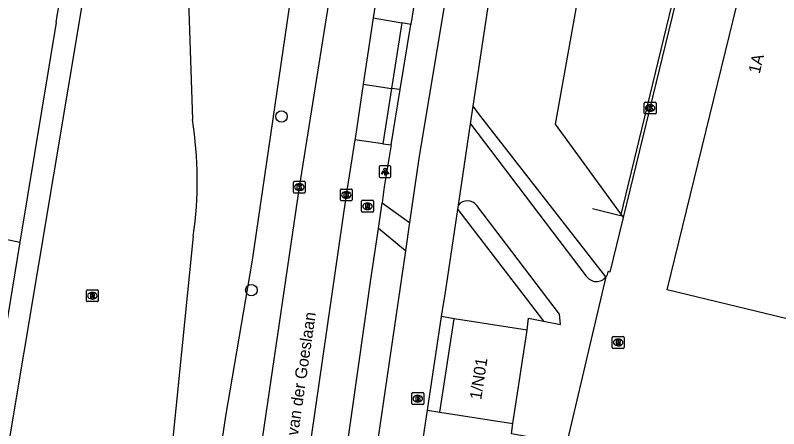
# Model space of a CAD drawing. Extents: x 163046 to 165074, y 382019 to 382874.
# Drawn here: x 163119.9 to 163184.8, y 382777.8 to 382812.9 of the extents above; entities that cross this region are included whole.
import ezdxf

# ---------------------------------------------------------------- set-up
doc = ezdxf.new("R2010")
doc.units = 0
for name, color, linetype in [('IMGEO_Berm_groen', 7, 'Continuous'), ('IMGEO_Berm_halfverhard', 7, 'Continuous'), ('IMGEO_Boom', 7, 'Continuous'), ('IMGEO_Brandkraan', 7, 'Continuous'), ('IMGEO_Fietspad_gesloten', 7, 'Continuous'), ('IMGEO_Fietspad_open', 7, 'Continuous'), ('IMGEO_Groenvoorziening', 7, 'Continuous'), ('IMGEO_Hek', 7, 'Continuous'), ('IMGEO_Kolk', 7, 'Continuous'), ('IMGEO_Lichtpunt', 7, 'Continuous'), ('IMGEO_Openbare_ruimte_label', 7, 'Continuous'), ('IMGEO_Pand', 7, 'Continuous'), ('IMGEO_Pand_nummerreeks', 7, 'Continuous'), ('IMGEO_Parkeervlak_open', 7, 'Continuous'), ('IMGEO_Rijbaan_lokaal_gesloten', 7, 'Continuous'), ('IMGEO_Rijbaan_lokaal_open', 7, 'Continuous'), ('IMGEO_Rioolput', 7, 'Continuous'), ('IMGEO_Voetpad_halfverhard', 7, 'Continuous'), ('IMGEO_Voetpad_open', 7, 'Continuous')]:
    doc.layers.add(name, color=color, linetype=linetype)

msp = doc.modelspace()

# ---------------------------------------------------------------- linework, layer by layer
at = {"layer": 'IMGEO_Berm_groen'}
for points in [[(163117.196, 382766.95), (163119.444, 382776.857), (163125.716, 382814.214), (163129.752, 382841.072)], [(163144.103, 382835.721), (163143.26, 382822.615), (163143.707, 382817.037), (163140.066, 382792.087), (163137.776, 382778.86), (163133.466, 382750), (163130.056, 382727.169)], [(163134.545, 382817.473), (163134.992, 382804.003)], [(163123.418, 382812.236), (163120.341, 382793.612)], [(163115.63, 382794.599), (163120.341, 382793.612)], [(163120.341, 382793.612), (163118.136, 382780.262)], [(163135.056, 382794.132), (163131.605, 382759.828), (163131.17, 382753.793), (163131.079, 382750), (163130.908, 382742.92), (163130.056, 382727.169)]]:
    msp.add_lwpolyline(points, dxfattribs=at)
for centre, radius, start, end in [((163009.489, 382831.398), 115.53, 350.45256, 356.35077), ((163101.746, 382798.852), 33.643, 351.93545, 8.80751)]:
    msp.add_arc(centre, radius, start, end, dxfattribs=at)
at = {"layer": 'IMGEO_Berm_halfverhard'}
for points in [[(163170.081, 382790.666), (163159.263, 382804.526), (163158.823, 382805.145)], [(163157.504, 382796.382), (163163.68, 382788.362), (163164.793, 382786.917)]]:
    msp.add_lwpolyline(points, dxfattribs=at)
at = {"layer": 'IMGEO_Boom'}
for centre in [(163142.541, 382804.272), (163139.988, 382789.546)]:
    msp.add_circle(centre, 0.489, dxfattribs=at)
at = {"layer": 'IMGEO_Brandkraan'}
for p, q in [((163153.61, 382779.927), (163153.61, 382780.779)), ((163153.685, 382780.853), (163154.537, 382780.853)), ((163154.611, 382780.779), (163154.611, 382779.927)), ((163154.121, 382780.073), (163154.096, 382780.073)), ((163154.098, 382780.633), (163154.123, 382780.633)), ((163154.537, 382779.853), (163153.685, 382779.853))]:
    msp.add_line(p, q, dxfattribs=at)
for points in [[(163153.61, 382779.927), (163153.61, 382780.779)], [(163153.685, 382780.853), (163154.537, 382780.853)], [(163154.611, 382780.779), (163154.611, 382779.927)], [(163153.958, 382780.553), (163153.958, 382780.153), (163154.171, 382780.153)], [(163154.189, 382780.553), (163153.958, 382780.553)], [(163154.137, 382780.472), (163154.083, 382780.472), (163154.083, 382780.396)], [(163154.083, 382780.396), (163154.136, 382780.396)], [(163154.145, 382780.32), (163154.083, 382780.32), (163154.083, 382780.239)], [(163154.083, 382780.239), (163154.145, 382780.239)], [(163154.537, 382779.853), (163153.685, 382779.853)]]:
    msp.add_lwpolyline(points, dxfattribs=at)
for centre, radius, start, end in [((163153.687, 382780.777), 0.0765, 91.55205, 178.44795), ((163153.687, 382780.777), 0.0765, 91.55205, 178.44795), ((163154.535, 382780.777), 0.0765, 1.55205, 88.44795), ((163154.535, 382780.777), 0.0765, 1.55205, 88.44795), ((163154.138, 382780.434), 0.0379, 267.82845, 90.93552), ((163154.146, 382780.279), 0.0404, 269.87594, 90.50774), ((163154.177, 382780.404), 0.251, 268.66757, 293.53466), ((163154.193, 382780.408), 0.145, 59.4692, 91.53667), ((163154.218, 382780.455), 0.0922, 285.51372, 58.15012), ((163154.223, 382780.263), 0.105, 301.31148, 78.98903), ((163153.687, 382779.929), 0.0765, 181.55205, 268.44795), ((163153.687, 382779.929), 0.0765, 181.55205, 268.44795), ((163154.535, 382779.929), 0.0765, 271.55205, 358.44795), ((163154.535, 382779.929), 0.0765, 271.55205, 358.44795)]:
    msp.add_arc(centre, radius, start, end, dxfattribs=at)
for centre, major_axis, ratio, start_param, end_param in [((163154.097, 382780.353), (-0.387, 0.002), 0.722429, 4.712389, 7.853982), ((163154.122, 382780.353), (-0.39, 0.002), 0.717154, 1.570796, 4.712389)]:
    msp.add_ellipse(centre, major_axis=major_axis, ratio=ratio, start_param=start_param, end_param=end_param, dxfattribs=at)
at = {"layer": 'IMGEO_Fietspad_gesloten'}
for points in [[(163161.113, 382845.228), (163160.864, 382844.839), (163160.254, 382840.645), (163156.415, 382813.95), (163154.228, 382800.916), (163153.406, 382795.273)], [(163157.332, 382836.53), (163153.568, 382812.405), (163153.528, 382812.16), (163153.515, 382812.081)], [(163151.849, 382801.853), (163152.616, 382806.559)], [(163151.849, 382801.853), (163151.271, 382798.302), (163151.077, 382796.956)], [(163151.077, 382796.956), (163153.406, 382795.273)], [(163147.509, 382772.212), (163147.935, 382775.112), (163150.138, 382790.439), (163150.763, 382794.772)], [(163153.058, 382792.885), (163150.763, 382794.772)], [(163153.058, 382792.885), (163150.245, 382773.595), (163147.259, 382753.463), (163143.616, 382727.869), (163141.748, 382715.527), (163141.421, 382713.325)]]:
    msp.add_lwpolyline(points, dxfattribs=at)
at = {"layer": 'IMGEO_Fietspad_open'}
for points in [[(163150.763, 382794.772), (163151.077, 382796.956)], [(163153.406, 382795.273), (163153.058, 382792.885)]]:
    msp.add_lwpolyline(points, dxfattribs=at)
at = {"layer": 'IMGEO_Groenvoorziening'}
for points in [[(163173.417, 382846.227), (163165.783, 382803.624), (163171.545, 382795.713)], [(163182.274, 382837.906), (163182.21, 382837.622), (163181.791, 382837.701), (163171.545, 382795.713)], [(163171.545, 382795.713), (163170.414, 382791.078), (163170.285, 382791.115)]]:
    msp.add_lwpolyline(points, dxfattribs=at)
msp.add_arc((163169.266, 382791.307), 1.037, 321.80581, 349.32551, dxfattribs=at)
at = {"layer": 'IMGEO_Hek'}
msp.add_lwpolyline([(163182.274, 382837.906), (163181.977, 382837.967), (163181.572, 382838.061), (163171.308, 382795.842), (163168.94, 382796.432)], dxfattribs=at)
at = {"layer": 'IMGEO_Kolk'}
for p, q in [((163173.336, 382804.562), (163173.336, 382805.414)), ((163173.411, 382805.488), (163174.263, 382805.488)), ((163173.824, 382805.268), (163173.849, 382805.268)), ((163174.337, 382805.414), (163174.337, 382804.562)), ((163173.847, 382804.708), (163173.822, 382804.708)), ((163174.263, 382804.488), (163173.411, 382804.488)), ((163143.632, 382798.78), (163144.484, 382798.78)), ((163143.557, 382797.854), (163143.557, 382798.706)), ((163144.045, 382798.56), (163144.07, 382798.56)), ((163144.558, 382798.706), (163144.558, 382797.854)), ((163144.484, 382797.78), (163143.632, 382797.78)), ((163144.068, 382798), (163144.043, 382798)), ((163147.545, 382797.19), (163147.545, 382798.042)), ((163147.62, 382798.116), (163148.472, 382798.116)), ((163148.033, 382797.896), (163148.058, 382797.896)), ((163148.546, 382798.042), (163148.546, 382797.19)), ((163148.472, 382797.116), (163147.62, 382797.116)), ((163148.056, 382797.336), (163148.031, 382797.336))]:
    msp.add_line(p, q, dxfattribs=at)
for points in [[(163173.336, 382804.562), (163173.336, 382805.414)], [(163173.411, 382805.488), (163174.263, 382805.488)], [(163174.337, 382805.414), (163174.337, 382804.562)], [(163173.657, 382805.188), (163173.78, 382805.188), (163173.78, 382805.037), (163173.91, 382805.188), (163174.074, 382805.188), (163173.928, 382805.037), (163174.081, 382804.788), (163173.929, 382804.788), (163173.844, 382804.952), (163173.78, 382804.885), (163173.78, 382804.788), (163173.657, 382804.788), (163173.657, 382805.188)], [(163174.263, 382804.488), (163173.411, 382804.488)], [(163143.632, 382798.78), (163144.484, 382798.78)], [(163143.557, 382797.854), (163143.557, 382798.706)], [(163143.878, 382798.48), (163144.001, 382798.48), (163144.001, 382798.329), (163144.131, 382798.48), (163144.295, 382798.48), (163144.149, 382798.329), (163144.302, 382798.08), (163144.15, 382798.08), (163144.065, 382798.244), (163144.001, 382798.177), (163144.001, 382798.08), (163143.878, 382798.08), (163143.878, 382798.48)], [(163144.558, 382798.706), (163144.558, 382797.854)], [(163144.484, 382797.78), (163143.632, 382797.78)], [(163147.545, 382797.19), (163147.545, 382798.042)], [(163147.62, 382798.116), (163148.472, 382798.116)], [(163147.866, 382797.816), (163147.989, 382797.816), (163147.989, 382797.665), (163148.119, 382797.816), (163148.283, 382797.816), (163148.137, 382797.665), (163148.29, 382797.416), (163148.138, 382797.416), (163148.053, 382797.58), (163147.989, 382797.513), (163147.989, 382797.416), (163147.866, 382797.416), (163147.866, 382797.816)], [(163148.546, 382798.042), (163148.546, 382797.19)], [(163148.472, 382797.116), (163147.62, 382797.116)]]:
    msp.add_lwpolyline(points, dxfattribs=at)
for centre, start, end in [((163173.413, 382805.412), 91.55205, 178.44795), ((163173.413, 382805.412), 91.55205, 178.44795), ((163174.261, 382805.412), 1.55205, 88.44795), ((163174.261, 382805.412), 1.55205, 88.44795), ((163173.413, 382804.564), 181.55205, 268.44795), ((163173.413, 382804.564), 181.55205, 268.44795), ((163174.261, 382804.564), 271.55205, 358.44795), ((163174.261, 382804.564), 271.55205, 358.44795), ((163143.634, 382798.704), 91.55205, 178.44795), ((163143.634, 382798.704), 91.55205, 178.44795), ((163144.482, 382798.704), 1.55205, 88.44795), ((163144.482, 382798.704), 1.55205, 88.44795), ((163143.634, 382797.856), 181.55205, 268.44795), ((163143.634, 382797.856), 181.55205, 268.44795), ((163144.482, 382797.856), 271.55205, 358.44795), ((163144.482, 382797.856), 271.55205, 358.44795), ((163147.622, 382798.04), 91.55205, 178.44795), ((163147.622, 382798.04), 91.55205, 178.44795), ((163148.47, 382798.04), 1.55205, 88.44795), ((163148.47, 382798.04), 1.55205, 88.44795), ((163147.622, 382797.192), 181.55205, 268.44795), ((163147.622, 382797.192), 181.55205, 268.44795), ((163148.47, 382797.192), 271.55205, 358.44795), ((163148.47, 382797.192), 271.55205, 358.44795)]:
    msp.add_arc(centre, 0.0765, start, end, dxfattribs=at)
for centre, major_axis, ratio, start_param, end_param in [((163173.823, 382804.988), (-0.387, 0.002), 0.722429, 4.712389, 7.853982), ((163173.848, 382804.988), (-0.39, 0.002), 0.717154, 1.570796, 4.712389), ((163144.044, 382798.28), (-0.387, 0.002), 0.722429, 4.712389, 7.853982), ((163144.069, 382798.28), (-0.39, 0.002), 0.717154, 1.570796, 4.712389), ((163148.032, 382797.616), (-0.387, 0.002), 0.722429, 4.712389, 7.853982), ((163148.057, 382797.616), (-0.39, 0.002), 0.717154, 1.570796, 4.712389)]:
    msp.add_ellipse(centre, major_axis=major_axis, ratio=ratio, start_param=start_param, end_param=end_param, dxfattribs=at)
at = {"layer": 'IMGEO_Lichtpunt'}
for p, q in [((163151.74, 382800.097), (163150.932, 382800.097)), ((163151.74, 382800.097), (163150.932, 382800.097)), ((163150.838, 382800.002), (163150.838, 382799.195)), ((163150.838, 382800.002), (163150.838, 382799.195)), ((163151.834, 382799.195), (163151.834, 382800.002)), ((163151.834, 382799.195), (163151.834, 382800.002)), ((163150.932, 382799.101), (163151.74, 382799.101)), ((163150.932, 382799.101), (163151.74, 382799.101))]:
    msp.add_line(p, q, dxfattribs=at)
for points in [[(163151.212, 382799.666), (163151.251, 382799.638), (163151.063, 382799.376), (163151.025, 382799.403), (163151.212, 382799.666)], [(163151.314, 382799.618), (163151.361, 382799.618), (163151.361, 382799.296), (163151.314, 382799.296), (163151.314, 382799.618)], [(163151.424, 382799.638), (163151.462, 382799.665), (163151.649, 382799.403), (163151.61, 382799.375), (163151.424, 382799.638)]]:
    msp.add_lwpolyline(points, dxfattribs=at)
msp.add_circle((163151.337, 382799.8), 0.0994, dxfattribs=at)
for centre, start, end in [((163150.932, 382800.002), 90, 180), ((163150.932, 382800.002), 90, 180), ((163151.74, 382800.002), 0, 90), ((163151.74, 382800.002), 0, 90), ((163150.932, 382799.195), 180, 270), ((163150.932, 382799.195), 180, 270), ((163151.74, 382799.195), 270, 0), ((163151.74, 382799.195), 270, 360)]:
    msp.add_arc(centre, 0.0946, start, end, dxfattribs=at)
at = {"layer": 'IMGEO_Pand'}
for points in [[(163187.293, 382745.549), (163188.39, 382750), (163192.114, 382765.114), (163195.861, 382780.592), (163193.706, 382781.12), (163194.64, 382784.88), (163189.274, 382786.194), (163188.807, 382784.289), (163185.83, 382784.999), (163186.289, 382786.912), (163175.289, 382789.564), (163181.211, 382813.835), (163184.927, 382829.066), (163223.479, 382819.666), (163229.289, 382818.246), (163225.61, 382803.159), (163234.14, 382801.079), (163234.934, 382804.334), (163235.333, 382804.237), (163228.809, 382777.497)], [(163155.996, 382779.19), (163157.203, 382787.107)], [(163163.387, 382786.165), (163157.203, 382787.107)], [(163162.18, 382778.247), (163163.387, 382786.165)], [(163155.996, 382779.19), (163162.18, 382778.247)]]:
    msp.add_lwpolyline(points, dxfattribs=at)
at = {"layer": 'IMGEO_Parkeervlak_open'}
msp.add_lwpolyline([(163151.156, 382801.951), (163148.773, 382802.288)], dxfattribs=at)
at = {"layer": 'IMGEO_Rijbaan_lokaal_gesloten'}
for points in [[(163133.078, 382728.993), (163133.75, 382730.587), (163134.348, 382732.415), (163134.652, 382734.165), (163134.996, 382736.383), (163136.998, 382750), (163137.687, 382754.683), (163140.785, 382775.983), (163144.059, 382798.28), (163147.602, 382820.471), (163149.65, 382831.634)], [(163153.583, 382830.888), (163150.907, 382816.447), (163150.331, 382812.628)], [(163150.331, 382812.628), (163149.485, 382807.011)], [(163149.485, 382807.011), (163148.791, 382802.404), (163148.773, 382802.288)], [(163148.773, 382802.288), (163148.045, 382797.616), (163144.417, 382772.599)]]:
    msp.add_lwpolyline(points, dxfattribs=at)
at = {"layer": 'IMGEO_Rijbaan_lokaal_open'}
for points in [[(163150.331, 382812.628), (163152.761, 382812.211)], [(163152.761, 382812.211), (163151.891, 382806.653)], [(163152.616, 382806.559), (163153.515, 382812.081)], [(163153.515, 382812.081), (163152.761, 382812.211)], [(163149.485, 382807.011), (163151.891, 382806.653)], [(163152.616, 382806.559), (163151.891, 382806.653)], [(163157.56, 382796.752), (163158.596, 382803.635)], [(163158.596, 382803.635), (163168.418, 382790.74)], [(163164.793, 382786.917), (163166.223, 382786.643), (163166.127, 382787.521), (163159.112, 382796.727)], [(163170.081, 382790.666), (163166.826, 382776.841), (163169.382, 382776.239), (163169.071, 382774.966)], [(163163.387, 382786.165), (163163.519, 382787.161), (163164.793, 382786.917)], [(163164.114, 382776.987), (163162.054, 382777.371), (163162.18, 382778.247)]]:
    msp.add_lwpolyline(points, dxfattribs=at)
for centre, radius, start, end in [((163158.326, 382796.131), 0.986, 37.19432, 140.95997), ((163169.276, 382791.301), 1.025, 213.19167, 321.71261)]:
    msp.add_arc(centre, radius, start, end, dxfattribs=at)
at = {"layer": 'IMGEO_Rioolput'}
for p, q in [((163149.343, 382796.237), (163149.343, 382797.089)), ((163149.418, 382797.163), (163150.27, 382797.163)), ((163149.831, 382796.943), (163149.856, 382796.943)), ((163150.344, 382797.089), (163150.344, 382796.237)), ((163149.854, 382796.383), (163149.829, 382796.383)), ((163150.27, 382796.163), (163149.418, 382796.163)), ((163125.988, 382788.643), (163125.988, 382789.495)), ((163126.063, 382789.569), (163126.915, 382789.569)), ((163126.476, 382789.349), (163126.501, 382789.349)), ((163126.989, 382789.495), (163126.989, 382788.643)), ((163126.915, 382788.569), (163126.063, 382788.569)), ((163126.499, 382788.789), (163126.474, 382788.789)), ((163170.618, 382784.682), (163170.618, 382785.534)), ((163170.693, 382785.608), (163171.545, 382785.608)), ((163171.106, 382785.388), (163171.131, 382785.388)), ((163171.619, 382785.534), (163171.619, 382784.682)), ((163171.545, 382784.608), (163170.693, 382784.608)), ((163171.129, 382784.828), (163171.104, 382784.828))]:
    msp.add_line(p, q, dxfattribs=at)
for points in [[(163149.343, 382796.237), (163149.343, 382797.089)], [(163149.418, 382797.163), (163150.27, 382797.163)], [(163149.932, 382796.861), (163149.68, 382796.863), (163149.68, 382796.463)], [(163150.344, 382797.089), (163150.344, 382796.237)], [(163149.68, 382796.463), (163149.804, 382796.463), (163149.804, 382796.625), (163149.815, 382796.625)], [(163149.858, 382796.782), (163149.804, 382796.782), (163149.804, 382796.701)], [(163149.804, 382796.701), (163149.856, 382796.701)], [(163149.862, 382796.596), (163149.933, 382796.463), (163150.073, 382796.463), (163150.008, 382796.589)], [(163150.27, 382796.163), (163149.418, 382796.163)], [(163125.988, 382788.643), (163125.988, 382789.495)], [(163126.063, 382789.569), (163126.915, 382789.569)], [(163126.577, 382789.267), (163126.325, 382789.269), (163126.325, 382788.869)], [(163126.503, 382789.188), (163126.449, 382789.188), (163126.449, 382789.107)], [(163126.449, 382789.107), (163126.501, 382789.107)], [(163126.989, 382789.495), (163126.989, 382788.643)], [(163126.915, 382788.569), (163126.063, 382788.569)], [(163126.325, 382788.869), (163126.449, 382788.869), (163126.449, 382789.031), (163126.46, 382789.031)], [(163126.507, 382789.002), (163126.578, 382788.869), (163126.718, 382788.869), (163126.653, 382788.995)], [(163170.618, 382784.682), (163170.618, 382785.534)], [(163170.693, 382785.608), (163171.545, 382785.608)], [(163171.207, 382785.306), (163170.955, 382785.308), (163170.955, 382784.908)], [(163171.133, 382785.227), (163171.079, 382785.227), (163171.079, 382785.146)], [(163171.619, 382785.534), (163171.619, 382784.682)], [(163171.545, 382784.608), (163170.693, 382784.608)], [(163170.955, 382784.908), (163171.079, 382784.908), (163171.079, 382785.07), (163171.09, 382785.07)], [(163171.079, 382785.146), (163171.131, 382785.146)], [(163171.137, 382785.041), (163171.208, 382784.908), (163171.348, 382784.908), (163171.283, 382785.034)]]:
    msp.add_lwpolyline(points, dxfattribs=at)
for centre, radius, start, end in [((163149.42, 382797.087), 0.0765, 91.55205, 178.44795), ((163149.42, 382797.087), 0.0765, 91.55205, 178.44795), ((163149.931, 382796.751), 0.109, 350.36119, 89.41601), ((163150.268, 382797.087), 0.0765, 1.55205, 88.44795), ((163150.268, 382797.087), 0.0765, 1.55205, 88.44795), ((163149.42, 382796.239), 0.0765, 181.55205, 268.44795), ((163149.42, 382796.239), 0.0765, 181.55205, 268.44795), ((163149.814, 382796.572), 0.0533, 26.02933, 88.69889), ((163149.84, 382796.89), 0.19, 274.7715, 282.96867), ((163149.864, 382796.686), 0.0964, 77.00612, 93.18647), ((163149.878, 382796.743), 0.0378, 276.66336, 79.67722), ((163149.929, 382796.751), 0.112, 277.58423, 350.98172), ((163149.913, 382796.536), 0.108, 29.51342, 73.79051), ((163150.268, 382796.239), 0.0765, 271.55205, 358.44795), ((163150.268, 382796.239), 0.0765, 271.55205, 358.44795), ((163126.065, 382789.493), 0.0765, 91.55205, 178.44795), ((163126.065, 382789.493), 0.0765, 91.55205, 178.44795), ((163126.485, 382789.296), 0.19, 274.7715, 282.96867), ((163126.509, 382789.092), 0.0964, 77.00612, 93.18647), ((163126.523, 382789.149), 0.0378, 276.66336, 79.67722), ((163126.576, 382789.157), 0.109, 350.36119, 89.41601), ((163126.574, 382789.157), 0.112, 277.58423, 350.98172), ((163126.913, 382789.493), 0.0765, 1.55205, 88.44795), ((163126.913, 382789.493), 0.0765, 1.55205, 88.44795), ((163126.065, 382788.645), 0.0765, 181.55205, 268.44795), ((163126.065, 382788.645), 0.0765, 181.55205, 268.44795), ((163126.459, 382788.978), 0.0533, 26.02933, 88.69889), ((163126.558, 382788.942), 0.108, 29.51342, 73.79051), ((163126.913, 382788.645), 0.0765, 271.55205, 358.44795), ((163126.913, 382788.645), 0.0765, 271.55205, 358.44795), ((163170.695, 382785.532), 0.0765, 91.55205, 178.44795), ((163170.695, 382785.532), 0.0765, 91.55205, 178.44795), ((163171.139, 382785.131), 0.0964, 77.00612, 93.18647), ((163171.153, 382785.188), 0.0378, 276.66336, 79.67722), ((163171.206, 382785.196), 0.109, 350.36119, 89.41601), ((163171.204, 382785.196), 0.112, 277.58423, 350.98172), ((163171.543, 382785.532), 0.0765, 1.55205, 88.44795), ((163171.543, 382785.532), 0.0765, 1.55205, 88.44795), ((163170.695, 382784.684), 0.0765, 181.55205, 268.44795), ((163170.695, 382784.684), 0.0765, 181.55205, 268.44795), ((163171.089, 382785.017), 0.0533, 26.02933, 88.69889), ((163171.115, 382785.335), 0.19, 274.7715, 282.96867), ((163171.188, 382784.981), 0.108, 29.51342, 73.79051), ((163171.543, 382784.684), 0.0765, 271.55205, 358.44795), ((163171.543, 382784.684), 0.0765, 271.55205, 358.44795)]:
    msp.add_arc(centre, radius, start, end, dxfattribs=at)
for centre, major_axis, ratio, start_param, end_param in [((163149.83, 382796.663), (-0.387, 0.002), 0.722429, 4.712389, 7.853982), ((163149.855, 382796.663), (-0.39, 0.002), 0.717154, 1.570796, 4.712389), ((163126.475, 382789.069), (-0.387, 0.002), 0.722429, 4.712389, 7.853982), ((163126.5, 382789.069), (-0.39, 0.002), 0.717154, 1.570796, 4.712389), ((163171.105, 382785.108), (-0.387, 0.002), 0.722429, 4.712389, 7.853982), ((163171.13, 382785.108), (-0.39, 0.002), 0.717154, 1.570796, 4.712389)]:
    msp.add_ellipse(centre, major_axis=major_axis, ratio=ratio, start_param=start_param, end_param=end_param, dxfattribs=at)
at = {"layer": 'IMGEO_Voetpad_halfverhard'}
for points in [[(163157.203, 382787.107), (163156.137, 382787.298)], [(163154.944, 382779.366), (163155.996, 382779.19)]]:
    msp.add_lwpolyline(points, dxfattribs=at)
at = {"layer": 'IMGEO_Voetpad_open'}
for points in [[(163158.823, 382805.145), (163161.538, 382823.186), (163164.825, 382845.479), (163167.195, 382845.104), (163167.534, 382847.364)], [(163151.891, 382806.653), (163151.156, 382801.951)], [(163158.596, 382803.635), (163158.823, 382805.145)], [(163151.156, 382801.951), (163151.849, 382801.853)], [(163156.137, 382787.298), (163156.45, 382789.376), (163157.504, 382796.382)], [(163157.504, 382796.382), (163157.56, 382796.752)], [(163154.944, 382779.366), (163156.137, 382787.298)], [(163154.119, 382773.886), (163154.605, 382777.113), (163154.944, 382779.366)]]:
    msp.add_lwpolyline(points, dxfattribs=at)

# ---------------------------------------------------------------- texts
at = {"layer": 'IMGEO_Openbare_ruimte_label'}
msp.add_text('Hugo van der Goeslaan', height=1, rotation=81.65913, dxfattribs=at).set_placement((163143.421, 382773.637))
at = {"layer": 'IMGEO_Pand_nummerreeks'}
for s, rotation, p in [('1A', 76.28843, (163183.125, 382807.845)), ('1/N01', 81.27761, (163159.494, 382780.206))]:
    msp.add_text(s, height=1, rotation=rotation, dxfattribs=at).set_placement(p)

doc.saveas('drawing.dxf')
